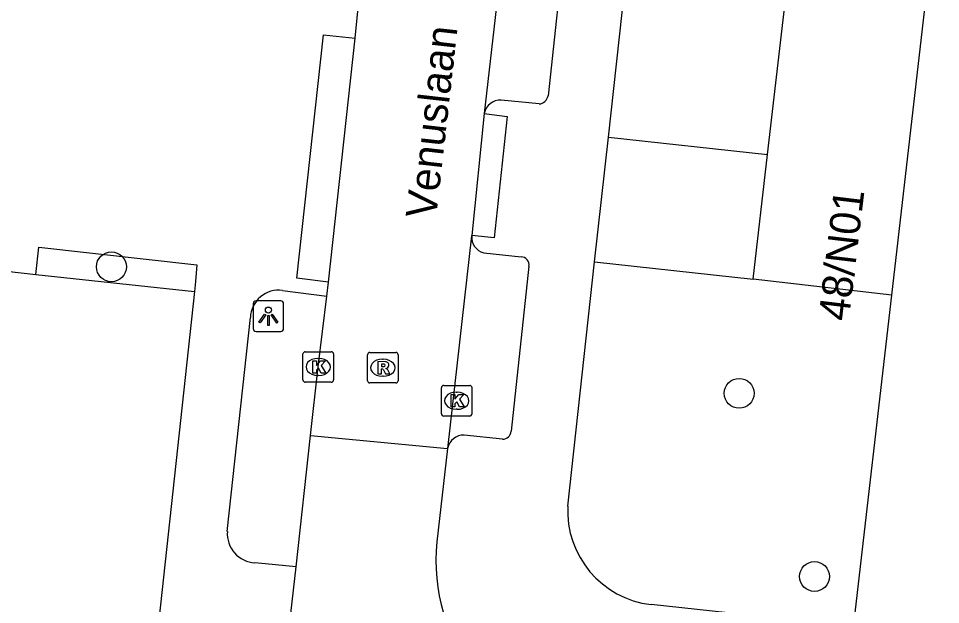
# Model space of a CAD drawing. Extents: x 161928 to 163055, y 386475 to 387428.
# Drawn here: x 162118.72 to 162148.91, y 387296.68 to 387315.88 of the extents above; entities that cross this region are included whole.
import ezdxf

# ---------------------------------------------------------------- set-up
doc = ezdxf.new("R2010")
doc.units = 0
for name, color, linetype in [('IMGEO_Boom', 7, 'Continuous'), ('IMGEO_Groenvoorziening', 7, 'Continuous'), ('IMGEO_Kolk', 7, 'Continuous'), ('IMGEO_Lichtpunt', 7, 'Continuous'), ('IMGEO_Muur', 7, 'Continuous'), ('IMGEO_Openbare_ruimte_label', 7, 'Continuous'), ('IMGEO_Pand', 7, 'Continuous'), ('IMGEO_Pand_nummerreeks', 7, 'Continuous'), ('IMGEO_Rijbaan_lokaal_open', 7, 'Continuous'), ('IMGEO_Rioolput', 7, 'Continuous'), ('IMGEO_Voetpad_open', 7, 'Continuous')]:
    doc.layers.add(name, color=color, linetype=linetype)

msp = doc.modelspace()

# ---------------------------------------------------------------- linework, layer by layer
at = {"layer": 'IMGEO_Boom'}
for centre in [(162121.766, 387307.743), (162142.315, 387303.599), (162144.781, 387297.599)]:
    msp.add_circle(centre, 0.489, dxfattribs=at)
at = {"layer": 'IMGEO_Groenvoorziening'}
msp.add_lwpolyline([(162146.056, 387295.944), (162147.309, 387306.81)], dxfattribs=at)
at = {"layer": 'IMGEO_Kolk'}
for p, q in [((162128.036, 387304.037), (162128.036, 387304.889)), ((162128.111, 387304.963), (162128.963, 387304.963)), ((162128.524, 387304.743), (162128.549, 387304.743)), ((162129.037, 387304.889), (162129.037, 387304.037)), ((162128.547, 387304.183), (162128.522, 387304.183)), ((162128.963, 387303.963), (162128.111, 387303.963)), ((162132.643, 387303.856), (162133.495, 387303.856)), ((162132.568, 387302.93), (162132.568, 387303.782)), ((162133.056, 387303.636), (162133.081, 387303.636)), ((162133.569, 387303.782), (162133.569, 387302.93)), ((162133.079, 387303.076), (162133.054, 387303.076)), ((162133.495, 387302.856), (162132.643, 387302.856))]:
    msp.add_line(p, q, dxfattribs=at)
for points in [[(162128.036, 387304.037), (162128.036, 387304.889)], [(162128.111, 387304.963), (162128.963, 387304.963)], [(162129.037, 387304.889), (162129.037, 387304.037)], [(162128.357, 387304.663), (162128.48, 387304.663), (162128.48, 387304.512), (162128.61, 387304.663), (162128.774, 387304.663), (162128.628, 387304.512), (162128.781, 387304.263), (162128.629, 387304.263), (162128.544, 387304.427), (162128.48, 387304.36), (162128.48, 387304.263), (162128.357, 387304.263), (162128.357, 387304.663)], [(162128.963, 387303.963), (162128.111, 387303.963)], [(162132.643, 387303.856), (162133.495, 387303.856)], [(162132.568, 387302.93), (162132.568, 387303.782)], [(162132.889, 387303.556), (162133.012, 387303.556), (162133.012, 387303.405), (162133.142, 387303.556), (162133.306, 387303.556), (162133.16, 387303.405), (162133.313, 387303.156), (162133.161, 387303.156), (162133.076, 387303.32), (162133.012, 387303.253), (162133.012, 387303.156), (162132.889, 387303.156), (162132.889, 387303.556)], [(162133.569, 387303.782), (162133.569, 387302.93)], [(162133.495, 387302.856), (162132.643, 387302.856)]]:
    msp.add_lwpolyline(points, dxfattribs=at)
for centre, start, end in [((162128.113, 387304.887), 91.552, 178.448), ((162128.113, 387304.887), 91.552, 178.448), ((162128.961, 387304.887), 1.552, 88.448), ((162128.961, 387304.887), 1.552, 88.448), ((162128.113, 387304.039), 181.552, 268.448), ((162128.113, 387304.039), 181.552, 268.448), ((162128.961, 387304.039), 271.552, 358.448), ((162128.961, 387304.039), 271.552, 358.448), ((162132.645, 387303.78), 91.552, 178.448), ((162132.645, 387303.78), 91.552, 178.448), ((162133.493, 387303.78), 1.552, 88.448), ((162133.493, 387303.78), 1.552, 88.448), ((162132.645, 387302.932), 181.552, 268.448), ((162132.645, 387302.932), 181.552, 268.448), ((162133.493, 387302.932), 271.552, 358.448), ((162133.493, 387302.932), 271.552, 358.448)]:
    msp.add_arc(centre, 0.0765, start, end, dxfattribs=at)
for centre, major_axis, ratio, start_param, end_param in [((162128.523, 387304.463), (-0.387, 0.002), 0.722429, 4.712389, 7.853982), ((162128.548, 387304.463), (-0.39, 0.002), 0.717154, 1.570796, 4.712389), ((162133.055, 387303.356), (-0.387, 0.002), 0.722429, 4.712389, 7.853982), ((162133.08, 387303.356), (-0.39, 0.002), 0.717154, 1.570796, 4.712389)]:
    msp.add_ellipse(centre, major_axis=major_axis, ratio=ratio, start_param=start_param, end_param=end_param, dxfattribs=at)
at = {"layer": 'IMGEO_Lichtpunt'}
for p, q in [((162126.405, 387306.529), (162126.405, 387305.722)), ((162126.405, 387306.529), (162126.405, 387305.722)), ((162127.307, 387306.624), (162126.499, 387306.624)), ((162127.307, 387306.624), (162126.499, 387306.624)), ((162127.401, 387305.722), (162127.401, 387306.529)), ((162127.401, 387305.722), (162127.401, 387306.529)), ((162126.499, 387305.628), (162127.307, 387305.628)), ((162126.499, 387305.628), (162127.307, 387305.628))]:
    msp.add_line(p, q, dxfattribs=at)
for points in [[(162126.779, 387306.193), (162126.818, 387306.165), (162126.63, 387305.903), (162126.592, 387305.93), (162126.779, 387306.193)], [(162126.881, 387306.145), (162126.928, 387306.145), (162126.928, 387305.823), (162126.881, 387305.823), (162126.881, 387306.145)], [(162126.991, 387306.165), (162127.029, 387306.192), (162127.216, 387305.93), (162127.177, 387305.902), (162126.991, 387306.165)]]:
    msp.add_lwpolyline(points, dxfattribs=at)
msp.add_circle((162126.904, 387306.327), 0.0994, dxfattribs=at)
for centre, start, end in [((162126.499, 387306.529), 90, 180), ((162126.499, 387306.529), 90, 180), ((162127.307, 387306.529), 0, 90), ((162127.307, 387306.529), 0, 90), ((162126.499, 387305.722), 180, 270), ((162126.499, 387305.722), 180, 270), ((162127.307, 387305.722), 270, 0), ((162127.307, 387305.722), 270, 360)]:
    msp.add_arc(centre, 0.0946, start, end, dxfattribs=at)
at = {"layer": 'IMGEO_Muur'}
for points in [[(162119.287, 387307.491), (162119.386, 387308.383), (162124.562, 387307.808), (162124.514, 387307.262), (162124.485, 387306.935)], [(162119.287, 387307.491), (162124.485, 387306.935)]]:
    msp.add_lwpolyline(points, dxfattribs=at)
at = {"layer": 'IMGEO_Pand'}
for points in [[(162143.245, 387311.421), (162144.372, 387321.189)], [(162147.309, 387306.81), (162148.907, 387320.667)], [(162142.774, 387307.333), (162143.245, 387311.421)], [(162147.309, 387306.81), (162142.774, 387307.333)]]:
    msp.add_lwpolyline(points, dxfattribs=at)
at = {"layer": 'IMGEO_Rijbaan_lokaal_open'}
for points in [[(162134.759, 387319.727), (162133.97, 387312.761)], [(162129.74, 387315.226), (162129.833, 387316.114), (162129.842, 387316.193)], [(162128.867, 387307.242), (162129.74, 387315.226)], [(162133.97, 387312.761), (162133.56, 387308.769)], [(162133.558, 387308.752), (162132.772, 387301.795)], [(162133.56, 387308.769), (162133.558, 387308.752)], [(162128.812, 387306.781), (162128.867, 387307.242)], [(162128.287, 387302.218), (162128.537, 387304.463), (162128.812, 387306.781)], [(162127.81, 387297.912), (162128.287, 387302.218)], [(162128.287, 387302.218), (162132.772, 387301.795)], [(162132.772, 387301.795), (162132.423, 387298.74)], [(162127.634, 387296.388), (162127.81, 387297.912)]]:
    msp.add_lwpolyline(points, dxfattribs=at)
msp.add_arc((162138.538, 387298.119), 6.147, 174.2036, 260.8433, dxfattribs=at)
at = {"layer": 'IMGEO_Rioolput'}
for p, q in [((162130.15, 387304.012), (162130.15, 387304.864)), ((162130.225, 387304.938), (162131.077, 387304.938)), ((162130.638, 387304.718), (162130.663, 387304.718)), ((162131.151, 387304.864), (162131.151, 387304.012)), ((162130.661, 387304.158), (162130.636, 387304.158)), ((162131.077, 387303.938), (162130.225, 387303.938))]:
    msp.add_line(p, q, dxfattribs=at)
for points in [[(162130.15, 387304.012), (162130.15, 387304.864)], [(162130.225, 387304.938), (162131.077, 387304.938)], [(162131.151, 387304.864), (162131.151, 387304.012)], [(162130.739, 387304.636), (162130.487, 387304.638), (162130.487, 387304.238)], [(162130.487, 387304.238), (162130.611, 387304.238), (162130.611, 387304.4), (162130.622, 387304.4)], [(162130.665, 387304.557), (162130.611, 387304.557), (162130.611, 387304.476)], [(162130.611, 387304.476), (162130.663, 387304.476)], [(162130.669, 387304.371), (162130.74, 387304.238), (162130.88, 387304.238), (162130.815, 387304.364)], [(162131.077, 387303.938), (162130.225, 387303.938)]]:
    msp.add_lwpolyline(points, dxfattribs=at)
for centre, radius, start, end in [((162130.227, 387304.862), 0.0765, 91.552, 178.448), ((162130.227, 387304.862), 0.0765, 91.552, 178.448), ((162131.075, 387304.862), 0.0765, 1.552, 88.448), ((162131.075, 387304.862), 0.0765, 1.552, 88.448), ((162130.621, 387304.347), 0.0533, 26.0293, 88.6989), ((162130.647, 387304.665), 0.19, 274.7715, 282.9687), ((162130.671, 387304.461), 0.0964, 77.0061, 93.1865), ((162130.685, 387304.518), 0.0378, 276.6634, 79.6772), ((162130.738, 387304.526), 0.109, 350.3612, 89.416), ((162130.736, 387304.526), 0.112, 277.5842, 350.9817), ((162130.72, 387304.311), 0.108, 29.5134, 73.7905), ((162130.227, 387304.014), 0.0765, 181.552, 268.448), ((162130.227, 387304.014), 0.0765, 181.552, 268.448), ((162131.075, 387304.014), 0.0765, 271.552, 358.448), ((162131.075, 387304.014), 0.0765, 271.552, 358.448)]:
    msp.add_arc(centre, radius, start, end, dxfattribs=at)
for centre, major_axis, ratio, start_param, end_param in [((162130.637, 387304.438), (-0.387, 0.002), 0.722429, 4.712389, 7.853982), ((162130.662, 387304.438), (-0.39, 0.002), 0.717154, 1.570796, 4.712389)]:
    msp.add_ellipse(centre, major_axis=major_axis, ratio=ratio, start_param=start_param, end_param=end_param, dxfattribs=at)
at = {"layer": 'IMGEO_Voetpad_open'}
for points in [[(162138.032, 387311.991), (162139.019, 387320.966), (162139.114, 387321.811)], [(162136.646, 387318.741), (162136.059, 387313.341)], [(162128.867, 387307.242), (162127.836, 387307.369), (162128.705, 387315.34), (162129.74, 387315.226)], [(162135.763, 387313.076), (162134.522, 387313.202)], [(162133.97, 387312.761), (162134.721, 387312.664), (162134.297, 387308.687), (162133.56, 387308.769)], [(162137.583, 387307.903), (162138.032, 387311.991)], [(162138.032, 387311.991), (162143.245, 387311.421)], [(162133.951, 387308.202), (162135.182, 387308.073)], [(162114.762, 387308.004), (162119.287, 387307.491)], [(162135.434, 387307.766), (162134.846, 387302.357)], [(162136.704, 387299.908), (162137.583, 387307.903)], [(162137.583, 387307.903), (162142.774, 387307.333)], [(162124.485, 387306.935), (162122.299, 387286.811)], [(162127.369, 387306.971), (162128.812, 387306.781)], [(162125.56, 387299.072), (162126.315, 387306.078)], [(162134.572, 387302.097), (162133.315, 387302.228)], [(162127.81, 387297.912), (162126.462, 387298.046)], [(162142.445, 387296.354), (162139.43, 387296.681)]]:
    msp.add_lwpolyline(points, dxfattribs=at)
for centre, radius, start, end in [((162134.498, 387312.666), 0.537, 87.4686, 169.775), ((162135.738, 387313.402), 0.327, 274.4164, 349.2579), ((162134.084, 387308.712), 0.527, 175.6769, 255.4182), ((162135.16, 387307.798), 0.276, 353.2696, 85.4919), ((162127.25, 387306.043), 0.936, 82.6871, 177.8587), ((162134.578, 387302.365), 0.268, 268.6245, 358.3719), ((162133.294, 387301.698), 0.531, 87.6845, 169.4548), ((162139.797, 387299.756), 3.097, 177.1821, 263.1966), ((162126.52, 387299.006), 0.962, 176.0931, 266.547)]:
    msp.add_arc(centre, radius, start, end, dxfattribs=at)

# ---------------------------------------------------------------- texts
at = {"layer": 'IMGEO_Openbare_ruimte_label'}
msp.add_text('Venuslaan', height=1, rotation=83.5713, dxfattribs=at).set_placement((162132.39, 387309.294))
at = {"layer": 'IMGEO_Pand_nummerreeks'}
msp.add_text('48/N01', height=1, rotation=83.1263, dxfattribs=at).set_placement((162145.9, 387305.939))

doc.saveas('drawing.dxf')
